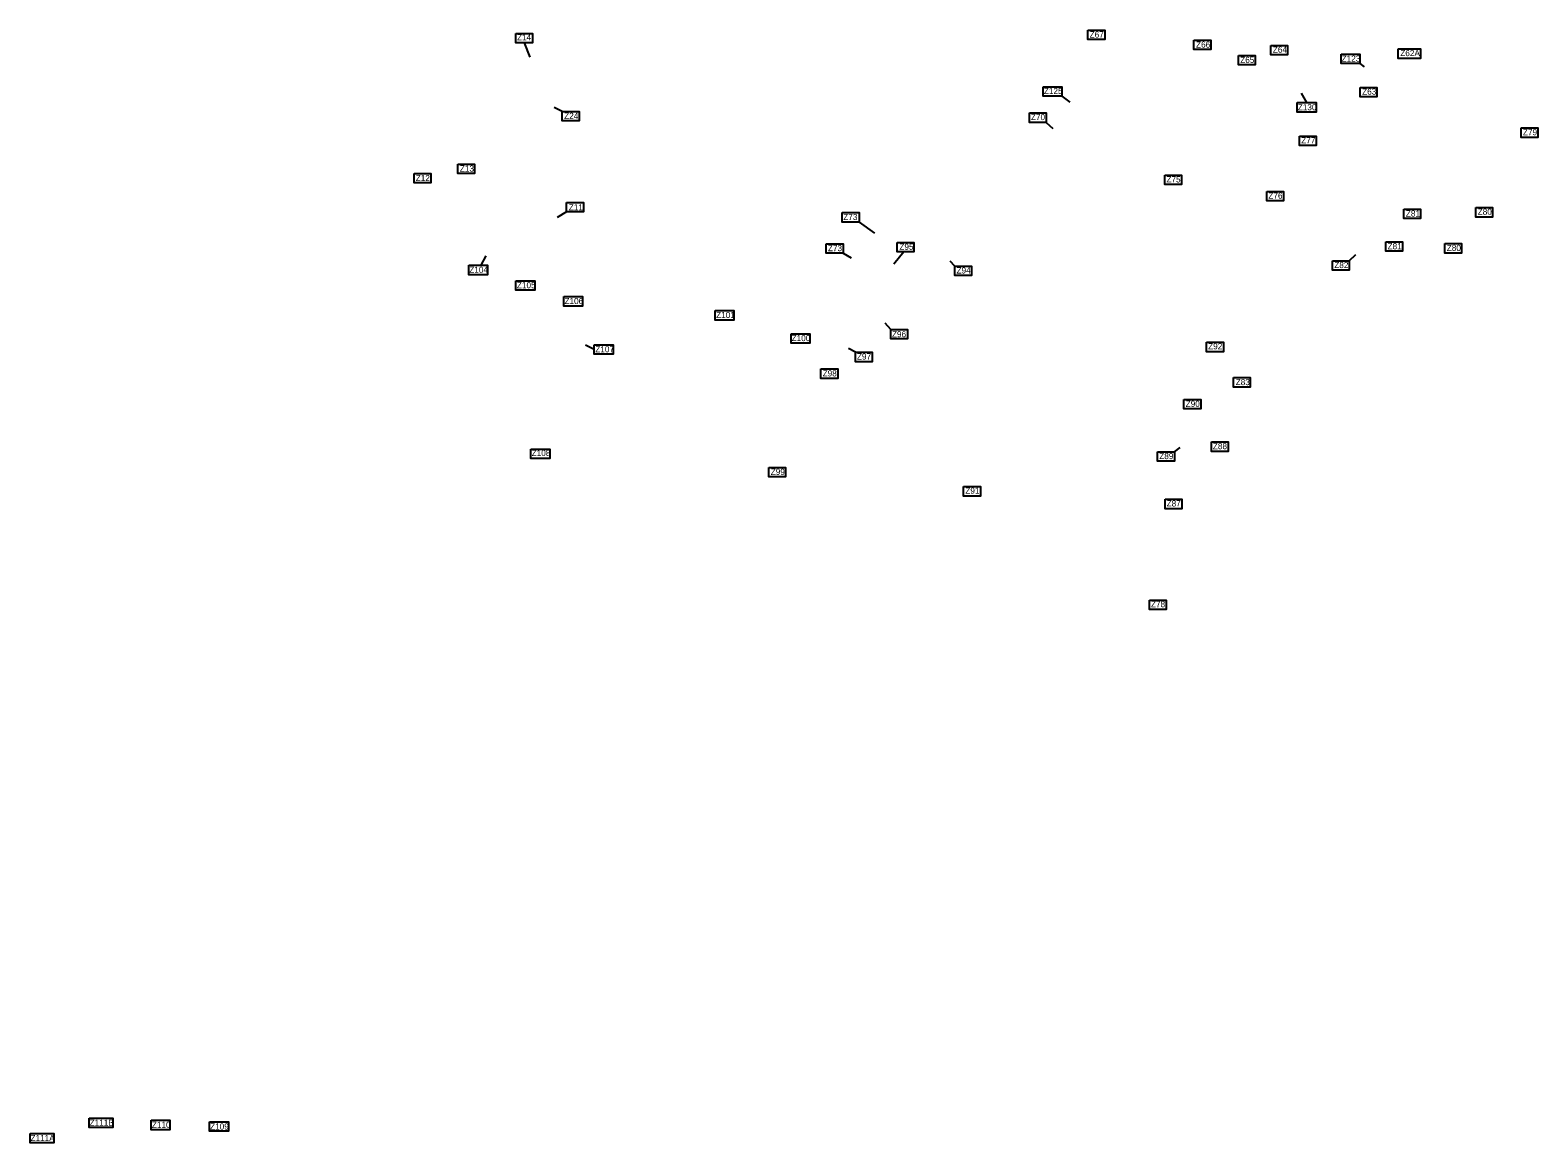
# Model space of a CAD drawing. Extents: x -443483 to -430840, y -1135277 to -1129797.
# Drawn here: x -443483 to -441026, y -1133472 to -1131658 of the extents above; entities that cross this region are included whole.
import ezdxf

# ---------------------------------------------------------------- set-up
doc = ezdxf.new("R2010")
doc.units = 0
doc.layers.add('Vrstva 3', color=7, linetype='Continuous')
doc.layers.add('Vrstva 8', color=7, linetype='Continuous')

msp = doc.modelspace()

# ---------------------------------------------------------------- linework, layer by layer
at = {"layer": 'Vrstva 3'}
for p, q in [((-442678, -1131678.5), (-442668.8, -1131701.8)), ((-442615.8, -1131790.2), (-442629.3, -1131783.8)), ((-441826.8, -1131808), (-441816.1, -1131818)), ((-442608.7, -1131954), (-442624.4, -1131962.9)), ((-442132.1, -1131970.6), (-442106.7, -1131988.4)), ((-442748.1, -1132041), (-442739.9, -1132025.7)), ((-442158.1, -1132021.3), (-442145, -1132028.8)), ((-442059.1, -1132019.3), (-442075.2, -1132039)), ((-441976.2, -1132042.2), (-441983.4, -1132034.2)), ((-441332.9, -1132033.8), (-441322.2, -1132023.2)), ((-442080.4, -1132145.5), (-442089.6, -1132135.5)), ((-442563.8, -1132178.3), (-442578.2, -1132171.1)), ((-442137.9, -1132182.9), (-442149.2, -1132176.8)), ((-441618.1, -1132344.9), (-441608.8, -1132338.2))]:
    msp.add_line(p, q, dxfattribs=at)
for points in [[(-442691.7, -1131663.1), (-442664.4, -1131663.1), (-442664.4, -1131678.5), (-442691.7, -1131678.5)], [(-441758.9, -1131657.7), (-441731.5, -1131657.7), (-441731.5, -1131673.1), (-441758.9, -1131673.1)], [(-441586.1, -1131673.9), (-441558.7, -1131673.9), (-441558.7, -1131689.3), (-441586.1, -1131689.3)], [(-441460.9, -1131682.5), (-441433.5, -1131682.5), (-441433.5, -1131697.9), (-441460.9, -1131697.9)], [(-441253.2, -1131688.3), (-441216.7, -1131688.3), (-441216.7, -1131703.7), (-441253.2, -1131703.7)], [(-441513.5, -1131699.1), (-441486.1, -1131699.1), (-441486.1, -1131714.5), (-441513.5, -1131714.5)], [(-441315.3, -1131751.1), (-441287.9, -1131751.1), (-441287.9, -1131766.5), (-441315.3, -1131766.5)], [(-442615.8, -1131790.2), (-442588.4, -1131790.2), (-442588.4, -1131805.6), (-442615.8, -1131805.6)], [(-441854.2, -1131792.6), (-441826.8, -1131792.6), (-441826.8, -1131808), (-441854.2, -1131808)], [(-441414.1, -1131830.4), (-441386.7, -1131830.4), (-441386.7, -1131845.8), (-441414.1, -1131845.8)], [(-441053, -1131817.2), (-441025.6, -1131817.2), (-441025.6, -1131832.6), (-441053, -1131832.6)], [(-442786.3, -1131876), (-442759, -1131876), (-442759, -1131891.4), (-442786.3, -1131891.4)], [(-442857.4, -1131891.3), (-442830, -1131891.3), (-442830, -1131906.7), (-442857.4, -1131906.7)], [(-441633.7, -1131893.9), (-441606.4, -1131893.9), (-441606.4, -1131909.3), (-441633.7, -1131909.3)], [(-442608.7, -1131938.6), (-442581.4, -1131938.6), (-442581.4, -1131954), (-442608.7, -1131954)], [(-441467.5, -1131920.6), (-441440.1, -1131920.6), (-441440.1, -1131936), (-441467.5, -1131936)], [(-442159.4, -1131955.2), (-442132.1, -1131955.2), (-442132.1, -1131970.6), (-442159.4, -1131970.6)], [(-441244, -1131949.4), (-441216.7, -1131949.4), (-441216.7, -1131964.8), (-441244, -1131964.8)], [(-441126.7, -1131946.9), (-441099.4, -1131946.9), (-441099.4, -1131962.3), (-441126.7, -1131962.3)], [(-442185.4, -1132005.9), (-442158.1, -1132005.9), (-442158.1, -1132021.3), (-442185.4, -1132021.3)], [(-442069.9, -1132003.9), (-442042.5, -1132003.9), (-442042.5, -1132019.3), (-442069.9, -1132019.3)], [(-441273.5, -1132002.7), (-441246.1, -1132002.7), (-441246.1, -1132018.1), (-441273.5, -1132018.1)], [(-441177.4, -1132005.6), (-441150, -1132005.6), (-441150, -1132021), (-441177.4, -1132021)], [(-441360.2, -1132033.8), (-441332.9, -1132033.8), (-441332.9, -1132049.2), (-441360.2, -1132049.2)], [(-442768.4, -1132041), (-442737.7, -1132041), (-442737.7, -1132056.4), (-442768.4, -1132056.4)], [(-441976.2, -1132042.2), (-441948.8, -1132042.2), (-441948.8, -1132057.6), (-441976.2, -1132057.6)], [(-442691.5, -1132066.2), (-442660.7, -1132066.2), (-442660.7, -1132081.6), (-442691.5, -1132081.6)], [(-442613.5, -1132092), (-442582.8, -1132092), (-442582.8, -1132107.4), (-442613.5, -1132107.4)], [(-442366.7, -1132114.8), (-442336, -1132114.8), (-442336, -1132130.2), (-442366.7, -1132130.2)], [(-442242.9, -1132152.5), (-442212.2, -1132152.5), (-442212.2, -1132167.9), (-442242.9, -1132167.9)], [(-442080.4, -1132145.5), (-442053.1, -1132145.5), (-442053.1, -1132160.9), (-442080.4, -1132160.9)], [(-442563.8, -1132170.6), (-442533.1, -1132170.6), (-442533.1, -1132186), (-442563.8, -1132186)], [(-442137.9, -1132182.9), (-442110.5, -1132182.9), (-442110.5, -1132198.2), (-442137.9, -1132198.2)], [(-441565.6, -1132166.6), (-441538.2, -1132166.6), (-441538.2, -1132181.9), (-441565.6, -1132181.9)], [(-442194.3, -1132209.9), (-442166.9, -1132209.9), (-442166.9, -1132225.3), (-442194.3, -1132225.3)], [(-441521.7, -1132224.2), (-441494.3, -1132224.2), (-441494.3, -1132239.6), (-441521.7, -1132239.6)], [(-441602.6, -1132259.7), (-441575.2, -1132259.7), (-441575.2, -1132275.1), (-441602.6, -1132275.1)], [(-441557.5, -1132329), (-441530.2, -1132329), (-441530.2, -1132344.4), (-441557.5, -1132344.4)], [(-442667.1, -1132340.5), (-442636.3, -1132340.5), (-442636.3, -1132355.9), (-442667.1, -1132355.9)], [(-441645.5, -1132344.9), (-441618.1, -1132344.9), (-441618.1, -1132360.3), (-441645.5, -1132360.3)], [(-442279.2, -1132370.4), (-442251.8, -1132370.4), (-442251.8, -1132385.8), (-442279.2, -1132385.8)], [(-441961.6, -1132401.7), (-441934.2, -1132401.7), (-441934.2, -1132417.1), (-441961.6, -1132417.1)], [(-441633.3, -1132422.4), (-441605.9, -1132422.4), (-441605.9, -1132437.8), (-441633.3, -1132437.8)], [(-441658.8, -1132586.9), (-441631.4, -1132586.9), (-441631.4, -1132602.3), (-441658.8, -1132602.3)], [(-443387, -1133431.3), (-443348.5, -1133431.3), (-443348.5, -1133446.7), (-443387, -1133446.7)], [(-443286.1, -1133434.8), (-443255.3, -1133434.8), (-443255.3, -1133450.2), (-443286.1, -1133450.2)], [(-443190.7, -1133437.1), (-443160, -1133437.1), (-443160, -1133452.5), (-443190.7, -1133452.5)], [(-443483.2, -1133456.1), (-443444.8, -1133456.1), (-443444.8, -1133471.5), (-443483.2, -1133471.5)], [(-443483.2, -1133456.1), (-443444.8, -1133456.1), (-443444.8, -1133471.5), (-443483.2, -1133471.5)]]:
    msp.add_lwpolyline(points, close=True, dxfattribs=at)
at = {"layer": 'Vrstva 8'}
for p, q in [((-441315.6, -1131712), (-441308.9, -1131717.3)), ((-441801.4, -1131765.3), (-441788.4, -1131775.3)), ((-441402.4, -1131775.9), (-441410.9, -1131760.6))]:
    msp.add_line(p, q, dxfattribs=at)
for points in [[(-441346.4, -1131696.6), (-441315.6, -1131696.6), (-441315.6, -1131712), (-441346.4, -1131712)], [(-441832.2, -1131749.9), (-441801.4, -1131749.9), (-441801.4, -1131765.3), (-441832.2, -1131765.3)], [(-441417.8, -1131775.9), (-441387.1, -1131775.9), (-441387.1, -1131791.3), (-441417.8, -1131791.3)]]:
    msp.add_lwpolyline(points, close=True, dxfattribs=at)

# ---------------------------------------------------------------- texts
at = {"layer": 'Vrstva 3'}
for s, p in [('Z14', (-442689.6, -1131674.5)), ('Z67', (-441756.2, -1131669.8)), ('Z66', (-441582.7, -1131686.2)), ('Z64', (-441457.5, -1131694.4)), ('Z62A', (-441249.8, -1131700.1)), ('Z65', (-441510.7, -1131711.2)), ('Z63', (-441311.9, -1131762.9)), ('Z24', (-442612.7, -1131802.4)), ('Z70', (-441851.9, -1131804.4)), ('Z77', (-441411.3, -1131842.4)), ('Z79', (-441049.9, -1131829)), ('Z13', (-442782.8, -1131888.3)), ('Z12', (-442854.7, -1131903.8)), ('Z75', (-441631, -1131906)), ('Z76', (-441464.8, -1131932.4)), ('Z11', (-442605.2, -1131951.5)), ('Z73', (-442157.8, -1131967.3)), ('Z81', (-441240.7, -1131961.6)), ('Z80', (-441123.6, -1131958.7)), ('Z73', (-442182.8, -1132018)), ('Z95', (-442066.3, -1132015.8)), ('Z81', (-441270.5, -1132014.9)), ('Z80', (-441174, -1132017.7)), ('Z82', (-441357.4, -1132045.6)), ('Z104', (-442767.4, -1132053.3)), ('Z94', (-441973.2, -1132054.4)), ('Z105', (-442689.8, -1132078.4)), ('Z106', (-442612.2, -1132104.3)), ('Z101', (-442365, -1132127)), ('Z100', (-442242, -1132164.7)), ('Z96', (-442078.4, -1132158.3)), ('Z107', (-442562, -1132182.9)), ('Z92', (-441563, -1132178)), ('Z97', (-442135.5, -1132194.7)), ('Z98', (-442191.4, -1132222.2)), ('Z83', (-441518.1, -1132236.4)), ('Z90', (-441599.6, -1132271.8)), ('Z88', (-441555.3, -1132340.8)), ('Z108', (-442665.7, -1132352)), ('Z89', (-441642.7, -1132357)), ('Z99', (-442276, -1132382.7)), ('Z91', (-441958.8, -1132413.4)), ('Z87', (-441630.7, -1132434.2)), ('Z78', (-441656.2, -1132598.4)), ('Z111B', (-443386.3, -1133443.6)), ('Z110', (-443284.8, -1133447.1)), ('Z111A', (-443482.6, -1133468.7)), ('Z109', (-443189.9, -1133449.9))]:
    msp.add_text(s, height=10, dxfattribs=at).set_placement(p)
at = {"layer": 'Vrstva 8'}
for s, p in [('Z123', (-441345.4, -1131709.1)), ('Z125', (-441830.8, -1131761.9)), ('Z130', (-441416.9, -1131788.4))]:
    msp.add_text(s, height=10, dxfattribs=at).set_placement(p)

doc.saveas('drawing.dxf')
